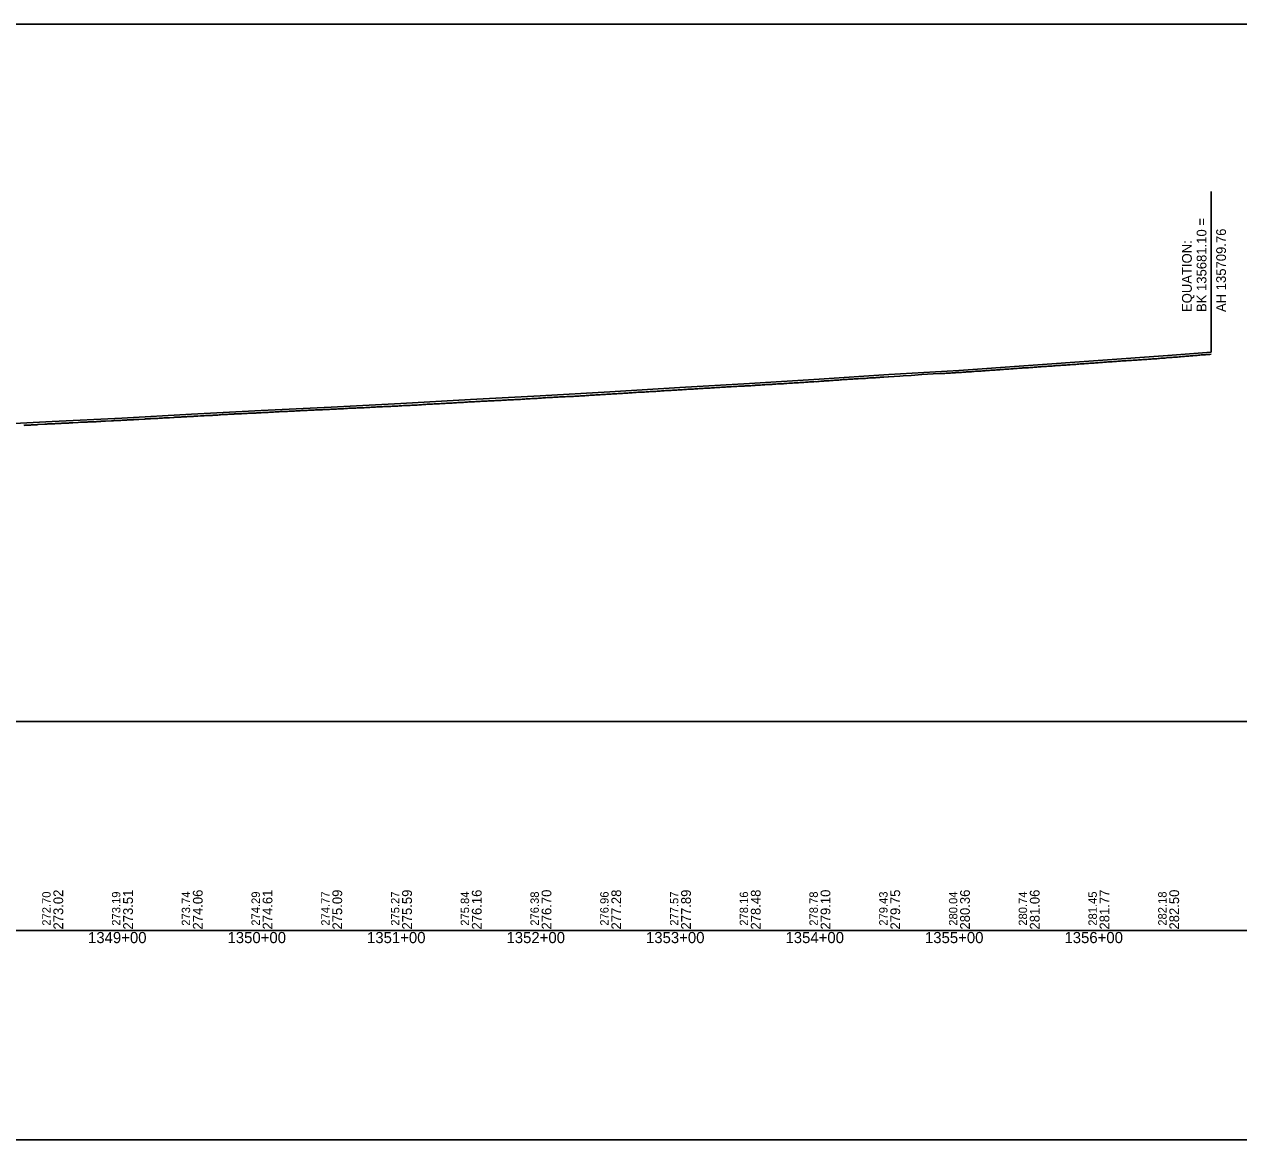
# Model space of a CAD drawing. Extents: x 2898 to 49495, y -15038 to -13538.
# Drawn here: x 24283 to 25154, y -15038 to -14238 of the extents above; entities that cross this region are included whole.
import ezdxf

# ---------------------------------------------------------------- set-up
doc = ezdxf.new("R2010")
doc.units = 0
for name, color, linetype in [('RD_DDB_Profile_EX', 7, 'Continuous'), ('RD_DDB_Profile_PR', 7, 'Continuous'), ('RD_DDB_StaTX', 7, 'Continuous'), ('RD_DDB_StripGrade', 7, 'Continuous'), ('RD_DDB_VCLbl', 7, 'Continuous'), ('RD_GPK_Profile_Cell', 7, 'Continuous'), ('RD_SHT_ShtClip', 7, 'Continuous')]:
    doc.layers.add(name, color=color, linetype=linetype)

msp = doc.modelspace()

# ---------------------------------------------------------------- linework, layer by layer
at = {"layer": 'RD_DDB_Profile_EX'}
for points in [[(24996.39, -14485.21), (24997.39, -14485.16), (24998.62, -14485.05), (24999.39, -14484.97), (25000.38, -14484.92), (25001.38, -14484.91), (25002.38, -14484.82), (25003.38, -14484.77), (25004.37, -14484.67), (25005.38, -14484.64), (25006.58, -14484.56), (25007.38, -14484.5), (25008.38, -14484.42), (25009.38, -14484.34), (25010.38, -14484.24), (25011.38, -14484.13), (25012.38, -14484.08), (25013.38, -14483.98), (25014.53, -14483.92), (25015.39, -14483.89), (25016.38, -14483.82), (25017.39, -14483.78), (25018.39, -14483.67), (25019.38, -14483.61), (25020.39, -14483.57), (25021.39, -14483.49), (25022.49, -14483.39), (25023.38, -14483.31), (25024.38, -14483.27), (25025.39, -14483.15), (25026.39, -14483.12), (25027.39, -14483.04), (25028.39, -14482.94), (25029.38, -14482.93), (25030.45, -14482.86), (25031.39, -14482.76), (25032.39, -14482.67), (25033.39, -14482.61), (25034.39, -14482.56), (25035.38, -14482.47), (25036.39, -14482.42), (25037.39, -14482.36), (25038.41, -14482.25), (25039.39, -14482.16), (25040.38, -14482.08), (25041.38, -14482.03), (25042.39, -14481.98), (25043.39, -14481.93), (25044.38, -14481.86), (25045.38, -14481.73), (25046.38, -14481.64), (25047.39, -14481.63), (25048.39, -14481.55), (25049.38, -14481.5), (25050.38, -14481.45), (25051.38, -14481.37), (25052.38, -14481.27), (25053.38, -14481.24), (25054.38, -14481.15), (25055.38, -14481.05), (25056.38, -14480.94), (25057.38, -14480.88), (25058.38, -14480.78), (25059.38, -14480.73), (25060.38, -14480.63), (25061.38, -14480.57), (25062.38, -14480.49), (25063.38, -14480.45), (25064.37, -14480.39), (25065.38, -14480.32), (25066.38, -14480.22), (25067.37, -14480.13), (25068.37, -14480.08), (25069.37, -14480), (25070.37, -14479.95), (25071.37, -14479.89), (25072.37, -14479.8), (25073.37, -14479.75), (25074.37, -14479.67), (25075.37, -14479.63), (25076.37, -14479.58), (25077.37, -14479.56), (25078.36, -14479.47), (25079.37, -14479.38), (25080.37, -14479.34), (25081.36, -14479.25), (25082.36, -14479.19), (25083.36, -14479.17), (25084.36, -14479.09), (25085.36, -14478.97), (25086.36, -14478.9), (25087.36, -14478.83), (25088.36, -14478.77), (25089.36, -14478.72), (25090.35, -14478.62), (25091.35, -14478.62), (25092.36, -14478.52), (25093.35, -14478.43), (25094.35, -14478.38), (25095.35, -14478.29), (25096.34, -14478.17)], [(25096.34, -14478.17), (25097.35, -14478.12), (25098.35, -14478.03), (25099.34, -14477.96), (25100.34, -14477.9), (25101.34, -14477.82), (25102.34, -14477.7), (25103.34, -14477.57), (25104.34, -14477.52), (25105.33, -14477.43), (25106.34, -14477.42), (25107.33, -14477.31), (25108.33, -14477.27), (25109.33, -14477.17), (25110.32, -14477.12), (25111.33, -14477.05), (25112.33, -14476.92), (25113.32, -14476.85), (25114.32, -14476.8), (25115.32, -14476.7), (25116.32, -14476.56), (25117.32, -14476.49), (25118.32, -14476.4), (25119.31, -14476.35), (25120.32, -14476.24), (25121.31, -14476.19), (25122.31, -14476.04), (25123.31, -14476), (25124.31, -14475.96), (25125.31, -14475.85), (25126.3, -14475.75), (25127.3, -14475.66), (25128.3, -14475.61), (25129.3, -14475.51), (25130.3, -14475.46), (25131.29, -14475.41), (25132.29, -14475.32), (25133.3, -14475.28), (25134.48, -14475.17)], [(24871.43, -14493.27), (24872.43, -14493.22), (24873.42, -14493.19), (24874.42, -14493.1), (24875.43, -14493.04), (24876.43, -14492.98), (24877.43, -14492.95), (24878.43, -14492.87), (24879.42, -14492.82), (24880.43, -14492.76), (24881.42, -14492.67), (24882.43, -14492.59), (24883.43, -14492.56), (24884.43, -14492.47), (24885.43, -14492.44), (24886.44, -14492.43), (24887.43, -14492.34), (24888.44, -14492.18), (24889.43, -14492.15), (24890.44, -14492.05), (24891.44, -14491.97), (24892.44, -14491.96), (24893.44, -14491.94), (24894.23, -14491.86), (24895.17, -14491.82), (24895.79, -14491.82), (24896.57, -14491.82), (24897.35, -14491.54), (24898.13, -14491.54), (24898.9, -14491.54), (24899.68, -14491.58), (24902.77, -14491.37), (24903.13, -14491.35), (24911.08, -14490.81), (24913.63, -14490.64), (24919.32, -14490.26), (24927, -14489.74), (24934.96, -14489.21), (24940.44, -14488.89), (24941.44, -14488.98), (24942.44, -14488.98), (24942.91, -14488.93), (24943.44, -14488.88), (24944.44, -14488.68), (24945.44, -14488.72), (24946.44, -14488.67), (24947.44, -14488.57), (24948.44, -14488.53), (24949.44, -14488.51), (24950.44, -14488.51), (24950.87, -14488.42), (24951.43, -14488.33), (24952.44, -14488.26), (24953.43, -14488.29), (24954.43, -14488.22), (24955.43, -14488.14), (24956.43, -14488.01), (24957.43, -14487.94), (24958.43, -14487.87), (24958.83, -14487.83), (24959.43, -14487.8), (24960.43, -14487.78), (24961.43, -14487.72), (24962.43, -14487.64), (24963.43, -14487.49), (24964.43, -14487.4), (24965.42, -14487.32), (24966.42, -14487.26), (24966.79, -14487.28), (24967.42, -14487.29), (24968.42, -14487.29), (24969.42, -14487.15), (24970.41, -14487.06), (24971.42, -14486.97), (24972.41, -14486.91), (24973.41, -14486.86), (24974.41, -14486.77), (24974.75, -14486.75), (24975.41, -14486.71), (24976.41, -14486.62), (24977.41, -14486.55), (24978.4, -14486.54), (24979.41, -14486.46), (24980.4, -14486.4), (24981.4, -14486.31), (24982.4, -14486.2), (24982.7, -14486.19), (24983.4, -14486.13), (24984.4, -14486.04), (24985.4, -14485.99), (24986.4, -14485.94), (24987.4, -14485.88), (24988.4, -14485.75), (24989.4, -14485.71), (24990.66, -14485.6), (24991.39, -14485.59), (24992.4, -14485.49), (24993.39, -14485.45), (24994.39, -14485.36), (24995.39, -14485.25), (24996.39, -14485.21)], [(24773.24, -14499.46), (24774.23, -14499.4), (24775.23, -14499.34), (24776.23, -14499.25), (24777.23, -14499.17), (24778.24, -14499.14), (24779.23, -14499.01), (24780.24, -14499.01), (24781.23, -14498.95), (24782.24, -14498.9), (24783.23, -14498.81), (24784.24, -14498.79), (24785.23, -14498.75), (24786.23, -14498.65), (24787.23, -14498.51), (24788.23, -14498.46), (24789.45, -14498.45), (24790.23, -14498.41), (24791.72, -14498.34), (24792.23, -14498.31), (24793.23, -14498.29), (24794.23, -14498.26), (24795.45, -14498.12), (24796.24, -14498.08), (24797.45, -14498.02), (24798.23, -14497.98), (24799.68, -14497.9), (24800.23, -14497.87), (24801.45, -14497.77), (24802.45, -14497.71), (24803.23, -14497.67), (24804.44, -14497.66), (24805.23, -14497.59), (24806.45, -14497.5), (24807.23, -14497.42), (24807.63, -14497.4), (24808.45, -14497.35), (24809.23, -14497.27), (24810.45, -14497.25), (24811.23, -14497.21), (24812.44, -14497.11), (24813.23, -14497.07), (24814.45, -14497), (24815.23, -14496.92), (24815.59, -14496.9), (24816.44, -14496.88), (24817.44, -14496.81), (24818.23, -14496.77), (24819.44, -14496.72), (24820.23, -14496.68), (24821.44, -14496.57), (24822.23, -14496.53), (24823.55, -14496.44), (24824.23, -14496.4), (24825.43, -14496.35), (24826.44, -14496.25), (24827.44, -14496.23), (24828.23, -14496.15), (24829.43, -14496.15), (24830.23, -14496.11), (24831.51, -14495.98), (24832.23, -14495.91), (24833.42, -14495.84), (24834.23, -14495.8), (24835.43, -14495.74), (24836.43, -14495.66), (24837.43, -14495.61), (24838.43, -14495.55), (24839.47, -14495.5), (24840.43, -14495.45), (24841.43, -14495.4), (24842.43, -14495.35), (24843.43, -14495.26), (24844.43, -14495.16), (24845.43, -14495.06), (24846.43, -14494.98), (24847.43, -14494.96), (24848.43, -14494.86), (24849.43, -14494.8), (24850.43, -14494.75), (24851.43, -14494.79), (24852.43, -14494.65), (24853.43, -14494.58), (24854.43, -14494.5), (24855.43, -14494.42), (24856.43, -14494.32), (24857.23, -14494.28), (24858.43, -14494.22), (24859.43, -14494.16), (24860.43, -14494.12), (24861.43, -14494.02), (24862.43, -14493.96), (24863.43, -14493.83), (24864.43, -14493.74), (24865.43, -14493.72), (24866.43, -14493.66), (24867.42, -14493.6), (24868.43, -14493.54), (24869.43, -14493.44), (24870.43, -14493.35), (24871.43, -14493.27)], [(24673.24, -14505.48), (24674.24, -14505.47), (24675.24, -14505.42), (24676.25, -14505.37), (24677.25, -14505.32), (24678.25, -14505.26), (24679.25, -14505.18), (24680.31, -14505.13), (24681.25, -14505.08), (24682.25, -14505.03), (24683.24, -14504.99), (24684.24, -14504.94), (24685.24, -14504.88), (24686.24, -14504.78), (24687.24, -14504.69), (24688.27, -14504.62), (24689.24, -14504.52), (24690.24, -14504.48), (24691.24, -14504.42), (24692.24, -14504.37), (24693.24, -14504.28), (24694.24, -14504.22), (24695.25, -14504.21), (24696.24, -14504.16), (24697.24, -14504.03), (24698.24, -14503.96), (24699.24, -14503.96), (24700.25, -14503.91), (24701.24, -14503.82), (24702.24, -14503.73), (24703.24, -14503.67), (24704.24, -14503.66), (24705.24, -14503.61), (24706.24, -14503.56), (24707.24, -14503.5), (24708.24, -14503.45), (24709.24, -14503.38), (24710.25, -14503.3), (24711.25, -14503.25), (24712.24, -14503.17), (24713.24, -14503.11), (24714.24, -14503.07), (24715.24, -14503.02), (24716.24, -14502.92), (24717.24, -14502.87), (24718.24, -14502.78), (24719.24, -14502.71), (24720.24, -14502.65), (24721.24, -14502.6), (24722.24, -14502.54), (24723.24, -14502.43), (24724.24, -14502.38), (24725.24, -14502.33), (24726.24, -14502.29), (24727.24, -14502.23), (24728.24, -14502.2), (24729.24, -14502.11), (24730.24, -14502.03), (24731.24, -14501.98), (24732.24, -14501.92), (24733.23, -14501.87), (24734.24, -14501.82), (24735.24, -14501.73), (24736.24, -14501.73), (24737.24, -14501.69), (24738.24, -14501.59), (24739.24, -14501.49), (24740.24, -14501.4), (24741.24, -14501.35), (24742.24, -14501.34), (24743.24, -14501.24), (24744.24, -14501.18), (24745.24, -14501.18), (24746.24, -14501.08), (24747.24, -14501.03), (24748.23, -14500.94), (24749.24, -14500.87), (24750.24, -14500.79), (24751.24, -14500.77), (24752.23, -14500.68), (24753.24, -14500.65), (24754.23, -14500.56), (24755.24, -14500.56), (24756.23, -14500.47), (24757.24, -14500.42), (24758.23, -14500.3), (24759.24, -14500.25), (24760.24, -14500.2), (24761.23, -14500.15), (24762.24, -14500.1), (24763.24, -14500.06), (24764.24, -14500.01), (24765.24, -14499.9), (24766.24, -14499.85), (24767.23, -14499.8), (24768.24, -14499.71), (24769.24, -14499.66), (24770.23, -14499.57), (24771.24, -14499.55), (24772.23, -14499.5), (24773.24, -14499.46)], [(24478.25, -14515.81), (24479.25, -14515.76), (24480.25, -14515.67), (24481.37, -14515.61), (24482.25, -14515.57), (24483.25, -14515.53), (24484.26, -14515.49), (24485.25, -14515.44), (24486.25, -14515.39), (24487.25, -14515.34), (24488.25, -14515.28), (24489.33, -14515.24), (24490.25, -14515.19), (24491.25, -14515.13), (24492.25, -14515.09), (24493.25, -14515.04), (24494.25, -14514.99), (24495.25, -14514.94), (24496.25, -14514.89), (24497.29, -14514.88), (24498.25, -14514.84), (24499.25, -14514.79), (24500.25, -14514.74), (24501.25, -14514.73), (24502.25, -14514.66), (24503.25, -14514.62), (24504.25, -14514.56), (24505.25, -14514.52), (24506.25, -14514.48), (24507.25, -14514.41), (24508.25, -14514.33), (24509.25, -14514.28), (24510.25, -14514.28), (24511.25, -14514.25), (24512.25, -14514.17), (24513.25, -14514.12), (24514.25, -14514.06), (24515.25, -14514.01), (24516.25, -14513.87), (24517.25, -14513.82), (24518.25, -14513.82), (24519.25, -14513.79), (24520.25, -14513.74), (24521.25, -14513.73), (24522.25, -14513.65), (24523.25, -14513.59), (24524.25, -14513.55), (24525.25, -14513.55), (24526.25, -14513.53), (24527.25, -14513.45), (24528.25, -14513.35), (24529.25, -14513.27), (24530.25, -14513.26), (24531.25, -14513.2), (24532.25, -14513.1), (24533.25, -14513.1), (24534.25, -14513.1), (24535.25, -14513.01), (24536.25, -14512.93), (24537.25, -14512.89), (24538.25, -14512.84), (24539.25, -14512.81), (24540.26, -14512.79), (24541.25, -14512.69), (24542.25, -14512.63), (24543.25, -14512.6), (24544.25, -14512.5), (24545.25, -14512.5), (24546.25, -14512.49), (24547.25, -14512.44), (24548.25, -14512.4), (24549.25, -14512.32), (24550.25, -14512.3), (24551.25, -14512.25), (24552.25, -14512.15), (24553.25, -14512.09), (24554.25, -14512.09), (24555.25, -14511.99), (24556.25, -14511.94), (24557.25, -14511.93), (24558.25, -14511.89), (24559.25, -14511.85), (24560.25, -14511.78), (24561.25, -14511.74), (24562.25, -14511.73), (24563.26, -14511.68), (24564.25, -14511.58), (24565.25, -14511.53), (24566.25, -14511.43), (24567.25, -14511.36), (24568.25, -14511.31), (24569.25, -14511.23), (24570.25, -14511.16), (24571.25, -14511.07), (24572.25, -14511.02), (24573.25, -14510.97), (24574.25, -14510.92), (24575.25, -14510.86), (24576.25, -14510.81), (24577.25, -14510.76), (24578.25, -14510.67)], [(24578.25, -14510.67), (24579.25, -14510.66), (24580.25, -14510.63), (24581.25, -14510.58), (24582.25, -14510.53), (24583.25, -14510.52), (24584.25, -14510.46), (24585.25, -14510.4), (24586.25, -14510.31), (24587.25, -14510.27), (24588.25, -14510.16), (24589.25, -14510.14), (24590.25, -14510.1), (24591.25, -14510.01), (24592.25, -14509.94), (24593.25, -14509.88), (24594.25, -14509.84), (24595.25, -14509.8), (24596.25, -14509.74), (24597.25, -14509.7), (24598.25, -14509.62), (24599.25, -14509.57), (24600.25, -14509.52), (24600.74, -14509.5), (24601.25, -14509.46), (24602.26, -14509.36), (24603.25, -14509.29), (24604.25, -14509.23), (24605.25, -14509.19), (24606.25, -14509.15), (24607.25, -14509.1), (24608.25, -14509.04), (24608.69, -14509), (24609.25, -14508.97), (24610.25, -14508.96), (24611.25, -14508.87), (24612.25, -14508.85), (24613.25, -14508.85), (24614.25, -14508.79), (24615.25, -14508.72), (24616.26, -14508.63), (24616.65, -14508.63), (24617.25, -14508.62), (24618.25, -14508.6), (24619.25, -14508.51), (24620.25, -14508.44), (24621.25, -14508.37), (24622.25, -14508.36), (24623.25, -14508.3), (24624.25, -14508.22), (24624.61, -14508.21), (24625.25, -14508.18), (24626.25, -14508.13), (24627.25, -14508.08), (24628.25, -14507.99), (24629.24, -14507.94), (24630.25, -14507.84), (24631.25, -14507.84), (24632.25, -14507.8), (24632.57, -14507.8), (24633.25, -14507.79), (24634.25, -14507.7), (24635.25, -14507.64), (24636.25, -14507.64), (24637.25, -14507.57), (24638.24, -14507.46), (24639.25, -14507.46), (24640.52, -14507.35), (24641.25, -14507.3), (24642.25, -14507.28), (24643.24, -14507.21), (24644.25, -14507.13), (24645.25, -14507.08), (24646.25, -14507.04), (24647.25, -14506.97), (24648.48, -14506.91), (24649.24, -14506.85), (24650.25, -14506.8), (24651.25, -14506.75), (24652.25, -14506.66), (24653.24, -14506.57), (24654.24, -14506.53), (24655.25, -14506.48), (24656.44, -14506.39), (24657.25, -14506.34), (24658.24, -14506.25), (24659.25, -14506.21), (24660.24, -14506.16), (24661.25, -14506.1), (24662.25, -14506.06), (24663.24, -14506.02), (24664.4, -14505.99), (24665.24, -14505.89), (24666.25, -14505.81), (24667.25, -14505.78), (24668.24, -14505.69), (24669.25, -14505.63), (24670.25, -14505.62), (24671.24, -14505.57), (24672.35, -14505.52), (24673.24, -14505.48)], [(24298.34, -14525.23), (24298.87, -14525.2), (24299.64, -14525.16), (24300.43, -14525.12), (24301.2, -14525.08), (24301.96, -14525.04), (24302.75, -14525.04), (24303.52, -14524.96), (24304.29, -14524.92), (24305.07, -14524.93), (24305.85, -14524.81), (24306.3, -14524.78), (24306.63, -14524.77), (24307.4, -14524.81), (24308.18, -14524.77), (24308.96, -14524.73), (24309.74, -14524.73), (24310.52, -14524.65), (24311.3, -14524.57), (24312.08, -14524.57), (24312.85, -14524.57), (24313.63, -14524.53), (24314.41, -14524.45), (24315.17, -14524.46), (24315.95, -14524.38), (24316.72, -14524.34), (24317.5, -14524.34), (24318.28, -14524.3), (24322.22, -14524.04), (24323.81, -14523.93), (24324.58, -14523.89), (24325.37, -14523.85), (24326.16, -14523.85), (24326.93, -14523.81), (24327.71, -14523.77), (24328.49, -14523.73), (24329.27, -14523.69), (24330.18, -14523.66), (24330.83, -14523.66), (24331.61, -14523.65), (24332.4, -14523.54), (24333.18, -14523.54), (24333.96, -14523.5), (24334.74, -14523.5), (24335.53, -14523.46), (24336.31, -14523.38), (24337.09, -14523.38), (24338.13, -14523.27), (24338.67, -14523.22), (24339.46, -14523.22), (24340.25, -14523.18), (24341.04, -14523.14), (24341.83, -14523.1), (24346.09, -14522.88), (24346.49, -14522.86), (24347.28, -14522.82), (24348.05, -14522.74), (24348.84, -14522.7), (24349.63, -14522.74), (24350.41, -14522.66), (24351.2, -14522.58), (24351.99, -14522.58), (24352.78, -14522.54), (24353.57, -14522.5), (24354.05, -14522.5), (24354.36, -14522.5), (24355.16, -14522.46), (24355.95, -14522.38), (24356.75, -14522.34), (24357.55, -14522.26), (24358.35, -14522.22), (24359.15, -14522.18), (24359.94, -14522.14), (24360.75, -14522.1), (24361.55, -14522.06), (24362.01, -14522.01), (24362.36, -14521.97), (24363.17, -14521.97), (24363.99, -14521.97), (24364.8, -14521.89), (24365.62, -14521.81), (24369.96, -14521.58), (24370.45, -14521.56), (24371.26, -14521.52), (24372.05, -14521.52), (24372.85, -14521.48), (24373.66, -14521.39), (24374.46, -14521.31), (24375.27, -14521.31), (24376.07, -14521.27), (24376.89, -14521.27), (24377.92, -14521.17), (24378.51, -14521.14), (24379.33, -14521.1), (24380.15, -14521.06), (24380.98, -14520.97), (24381.8, -14520.93), (24382.62, -14520.85), (24383.43, -14520.81), (24384.25, -14520.77), (24385.07, -14520.77)], [(24385.07, -14520.77), (24385.89, -14520.65), (24386.7, -14520.61), (24387.52, -14520.61), (24390.72, -14520.38), (24391.54, -14520.34), (24392.36, -14520.3), (24393.19, -14520.26), (24394, -14520.18), (24394.82, -14520.18), (24395.63, -14520.14), (24396.45, -14520.1), (24397.27, -14520.06), (24398.08, -14520.02), (24398.89, -14519.97), (24399.7, -14519.93), (24400.51, -14519.85), (24401.32, -14519.85), (24401.79, -14519.83), (24402.14, -14519.81), (24402.95, -14519.77), (24403.76, -14519.73), (24404.57, -14519.69), (24405.38, -14519.61), (24406.19, -14519.57), (24407, -14519.53), (24407.81, -14519.53), (24409.75, -14519.39), (24412.53, -14519.19), (24413.33, -14519.15), (24414.14, -14519.11), (24414.97, -14519.02), (24415.77, -14519.02), (24416.58, -14518.98), (24417.4, -14518.98), (24417.71, -14518.97), (24418.21, -14518.94), (24419.01, -14518.86), (24419.83, -14518.82), (24420.64, -14518.82), (24421.45, -14518.78), (24422.26, -14518.74), (24423.26, -14518.54), (24424.26, -14518.49), (24425.26, -14518.44), (24425.67, -14518.44), (24426.26, -14518.43), (24427.26, -14518.38), (24428.26, -14518.33), (24429.26, -14518.25), (24430.25, -14518.19), (24431.25, -14518.19), (24432.26, -14518.15), (24433.26, -14518.05), (24433.62, -14518.01), (24434.26, -14517.96), (24435.26, -14517.95), (24436.26, -14517.91), (24437.25, -14517.86), (24438.25, -14517.84), (24439.26, -14517.78), (24440.25, -14517.68), (24441.25, -14517.6), (24441.58, -14517.6), (24442.26, -14517.6), (24443.26, -14517.55), (24444.26, -14517.49), (24445.25, -14517.45), (24446.26, -14517.39), (24447.25, -14517.38), (24448.25, -14517.34), (24449.54, -14517.26), (24450.26, -14517.19), (24451.25, -14517.14), (24452.25, -14517.08), (24453.26, -14517.03), (24454.25, -14516.98), (24455.25, -14516.96), (24456.25, -14516.92), (24457.5, -14516.89), (24458.25, -14516.84), (24459.25, -14516.72), (24460.26, -14516.71), (24461.25, -14516.64), (24462.25, -14516.6), (24463.25, -14516.52), (24464.25, -14516.52), (24465.46, -14516.46), (24466.25, -14516.39), (24467.25, -14516.27), (24468.25, -14516.22), (24469.25, -14516.22), (24470.25, -14516.17), (24471.25, -14516.12), (24472.25, -14516.1), (24473.41, -14516.04), (24474.25, -14516.01), (24475.25, -14515.97), (24476.25, -14515.92), (24477.25, -14515.86), (24478.25, -14515.81)], [(24283.18, -14526.11), (24283.96, -14526.03), (24284.74, -14525.99), (24285.52, -14525.95), (24286.29, -14525.91), (24287.07, -14525.88), (24287.84, -14525.88), (24288.63, -14525.84), (24289.4, -14525.8), (24290.39, -14525.75), (24290.94, -14525.72), (24291.72, -14525.68), (24292.51, -14525.64), (24293.28, -14525.57), (24298.34, -14525.23)]]:
    msp.add_lwpolyline(points, dxfattribs=at)
at = {"layer": 'RD_DDB_Profile_PR'}
msp.add_lwpolyline([(24253.38, -14526), (24303.38, -14523.38), (24353.38, -14520.91), (24403.38, -14518.15), (24453.38, -14515.42), (24503.38, -14513.01), (24553.38, -14510.49), (24603.38, -14507.68), (24653.38, -14504.97), (24703.38, -14502.07), (24753.38, -14499.03), (24803.38, -14496.07), (24853.38, -14492.99), (24903.38, -14489.73), (24953.38, -14486.69), (25003.38, -14483.17), (25053.38, -14479.64), (25103.38, -14475.96), (25134.48, -14473.64)], dxfattribs=at)
at = {"layer": 'RD_DDB_VCLbl'}
for p, q in [((25134.48, -14473.64), (25134.48, -14358.44)), ((25134.48, -14475.17), (25134.48, -14475.17))]:
    msp.add_line(p, q, dxfattribs=at)
at = {"layer": 'RD_GPK_Profile_Cell'}
msp.add_line((2976.05, -14888.47), (48721.13, -14888.47), dxfattribs=at)
at = {"layer": 'RD_SHT_ShtClip'}
for points in [[(23975.38, -14238.47), (23975.38, -14738.47), (25475.38, -14738.47), (25475.38, -14738.47), (25475.38, -14238.47), (25475.38, -14238.47)], [(23955.38, -14738.47), (25495.38, -14738.47), (25495.38, -15038.47), (23955.38, -15038.47)]]:
    msp.add_lwpolyline(points, close=True, dxfattribs=at)

# ---------------------------------------------------------------- texts
at = {"layer": 'RD_DDB_Profile_PR'}
for s, p in [('BK 135681.10 =', (25130.98, -14444.84)), ('AH 135709.76', (25144.98, -14444.84)), ('EQUATION:', (25120.48, -14444.84))]:
    msp.add_text(s, height=7, rotation=90, dxfattribs=at).set_placement(p)
at = {"layer": 'RD_DDB_StaTX'}
for s, p in [('1349+00', (24329.18, -14897.47)), ('1350+00', (24429.18, -14897.47)), ('1351+00', (24529.18, -14897.47)), ('1352+00', (24629.18, -14897.47)), ('1353+00', (24729.18, -14897.47)), ('1354+00', (24829.18, -14897.47)), ('1355+00', (24929.18, -14897.47)), ('1356+00', (25029.18, -14897.47))]:
    msp.add_text(s, height=8, dxfattribs=at).set_placement(p)
at = {"layer": 'RD_DDB_StripGrade'}
for s, height, p in [('272.70', 6, (24302.38, -14884.98)), ('273.02', 7, (24311.38, -14887.72)), ('273.19', 6, (24352.38, -14884.98)), ('273.51', 7, (24361.38, -14887.72)), ('273.74', 6, (24402.38, -14884.98)), ('274.06', 7, (24411.38, -14887.72)), ('274.29', 6, (24452.38, -14884.98)), ('274.61', 7, (24461.38, -14887.72)), ('274.77', 6, (24502.38, -14884.98)), ('275.09', 7, (24511.38, -14887.72)), ('275.27', 6, (24552.38, -14884.98)), ('275.59', 7, (24561.38, -14887.72)), ('275.84', 6, (24602.38, -14884.98)), ('276.16', 7, (24611.38, -14887.72)), ('276.38', 6, (24652.38, -14884.98)), ('276.70', 7, (24661.38, -14887.72)), ('276.96', 6, (24702.38, -14884.98)), ('277.28', 7, (24711.38, -14887.72)), ('277.57', 6, (24752.38, -14884.98)), ('277.89', 7, (24761.38, -14887.72)), ('278.16', 6, (24802.38, -14884.98)), ('278.48', 7, (24811.38, -14887.72)), ('278.78', 6, (24852.38, -14884.98)), ('279.10', 7, (24861.38, -14887.72)), ('279.43', 6, (24902.38, -14884.98)), ('279.75', 7, (24911.38, -14887.72)), ('280.04', 6, (24952.38, -14884.98)), ('280.36', 7, (24961.38, -14887.72)), ('280.74', 6, (25002.38, -14884.98)), ('281.06', 7, (25011.38, -14887.72)), ('281.45', 6, (25052.38, -14884.98)), ('281.77', 7, (25061.38, -14887.72)), ('282.18', 6, (25102.38, -14884.98)), ('282.50', 7, (25111.38, -14887.72))]:
    msp.add_text(s, height=height, rotation=90, dxfattribs=at).set_placement(p)

doc.saveas('drawing.dxf')
